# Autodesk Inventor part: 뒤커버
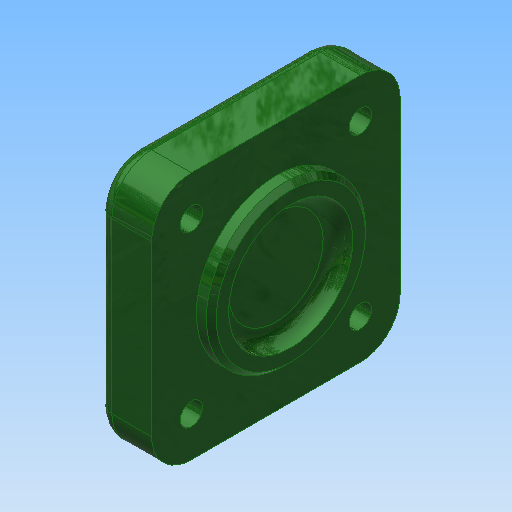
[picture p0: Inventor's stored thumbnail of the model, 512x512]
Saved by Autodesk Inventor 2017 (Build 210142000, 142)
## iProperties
Created: 2018-07
Part Number: 뒤커버
Material: 알루미늄 6061
Document SubType Name: Modeling
Designer: mduedu
Density: 1 g/cm^3
Appearance: 매끄러움 - 짙은 산림 녹색
Author: mduedu
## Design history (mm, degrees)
sketch "스케치1"
  geometry: C1 r 16 at (0, 0); 1 further point
  constraints: 1 centre point, 1 coincident
  dimensions: "d0" = 32 diameter of C1
extrude "돌출1" new body sketch "스케치1" distance "d1" = 3; taper "d2" = 0 deg
sketch "스케치2"
  geometry: L1 (-25, -25)-(25, -25); L2 (25, -25)-(25, 25); L3 (25, 25)-(-25, 25); L4 (-25, 25)-(-25, -25); L5 (-25, -25)-(25, 25); L6 (25, -25)-(-25, 25); 1 further point
  constraints: 12 end point, 2 midpoint, 2 parallel, 1 horizontal, 1 perpendicular
  dimensions: "d3" = 50 distance of L3.end L2.end; "d4" = 50 distance of L2.end L1.end
extrude "돌출2" join sketch "스케치2" distance "d5" = 11; taper "d6" = 0 deg
hole "구멍1" diameter "d9" = 25; stored, may be unused: countersink angle "d13" = 90 deg, drill point angle "d15" = 0 deg; dims "d7" = 10, "d8" = 10, "d10" = 6, "d11" = 4, "d12" = 2, "d14" = 3
fillet "모깎기2" dims "d26" = 3
fillet "모깎기3" dims "d27" = 8
sketch "스케치5"
  geometry: L1 (25, -17)-(25, 17) reference; L2 (17, 25)-(-17, 25) reference; L3 (-25, 17)-(-25, -17) reference; L4 (-17, -25)-(17, -25) reference; A1 r 8 centre (17, -17) between (17, -25) and (25, -17) reference; A2 r 8 centre (17, 17) between (25, 17) and (17, 25) reference; A3 r 8 centre (-17, 17) between (-17, 25) and (-25, 17) reference; A4 r 8 centre (-17, -17) between (-25, -17) and (-17, -25) reference; 5 further points
  constraints: 4 coincident
hole "구멍2" sketch "스케치5" at (-17, 17), (17, 17), (17, -17), (-17, -17) diameter "d28" = 4.5; stored, may be unused: countersink angle "d32" = 90 deg, drill point angle "d34" = 0 deg; dims "d29" = 6, "d30" = 8, "d31" = 4.6, "d33" = 3
fillet "모깎기4" dims "d35" = 3
chamfer "모따기2" distance "d36" = 1; stored, may be unused: second distance "d37" = 2, angle "d38" = 45 deg
node "솔리드1"
node "투영된 루프1"
